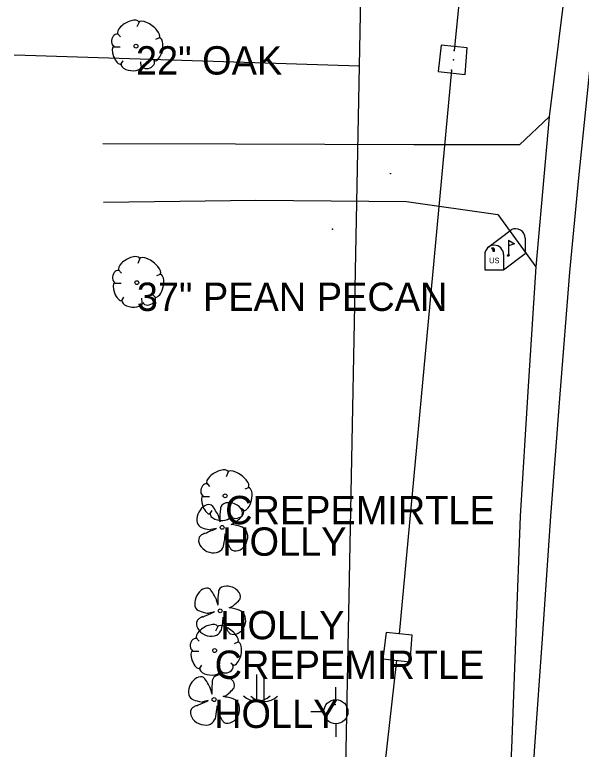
# Model space of a CAD drawing. Extents: x 1930288 to 1941089, y 588389 to 611475.
# Drawn here: x 1930774.6 to 1930874.5, y 598322 to 598451.6 of the extents above; entities that cross this region are included whole.
import ezdxf

# ---------------------------------------------------------------- set-up
doc = ezdxf.new("R2010")
doc.units = 0
for name, color, linetype in [('S_DRG_PT_SYM', 7, 'Continuous'), ('S_DRIVEWAY', 7, 'Continuous'), ('S_DROP_INLET', 7, 'Continuous'), ('S_EDGE_PAVEMENT', 7, 'Continuous'), ('S_GAS_UTILITIES', 7, 'Continuous'), ('S_MAILBOX', 7, 'Continuous'), ('S_MSC_PT_SYM', 7, 'Continuous'), ('S_SHOULDER', 7, 'Continuous'), ('S_STORM_SEWER', 7, 'Continuous'), ('S_TREE', 7, 'Continuous'), ('S_TREE_ANNOT', 7, 'Continuous'), ('S_UTILITY_POLE', 7, 'Continuous'), ('S_UTL_PT_SYM', 7, 'Continuous'), ('S_WATER_UTILITIES', 7, 'Continuous')]:
    doc.layers.add(name, color=color, linetype=linetype)

msp = doc.modelspace()

# ---------------------------------------------------------------- linework, layer by layer
at = {"layer": 'S_DRG_PT_SYM'}
msp.add_lwpolyline([(1930851.96, 598443.64), (1930851.96, 598443.69), (1930851.96, 598443.64), (1930851.91, 598443.64), (1930851.96, 598443.64), (1930851.96, 598443.59), (1930851.96, 598443.64), (1930852.01, 598443.64)], dxfattribs=at)
at = {"layer": 'S_DRIVEWAY'}
for points in [[(1930868.81, 598433.59), (1930863.6, 598428.65), (1930844.97, 598428.6), (1930829.25, 598428.67), (1930813.54, 598428.73), (1930790.14, 598428.8)], [(1930790.26, 598418.52), (1930803.67, 598418.69), (1930817.08, 598418.87), (1930830.39, 598418.75), (1930843.69, 598418.64), (1930859.8, 598416.35), (1930866.47, 598407.12)]]:
    msp.add_lwpolyline(points, dxfattribs=at)
at = {"layer": 'S_DROP_INLET'}
for points in [[(1930849.8, 598446.24), (1930849.25, 598441.56), (1930854.02, 598441.03), (1930854.39, 598445.77)], [(1930854.39, 598445.77), (1930849.8, 598446.24)], [(1930840.06, 598342.61), (1930839.52, 598337.93), (1930844.29, 598337.4), (1930844.66, 598342.14)], [(1930844.66, 598342.14), (1930840.06, 598342.61)]]:
    msp.add_lwpolyline(points, dxfattribs=at)
at = {"layer": 'S_EDGE_PAVEMENT'}
msp.add_lwpolyline([(1930877.33, 598456.1), (1930875.68, 598439.46), (1930874.03, 598422.82), (1930872.39, 598406.18), (1930870.73, 598384.64), (1930869.07, 598363.1), (1930867.63, 598342.37), (1930866.18, 598321.65), (1930865.17, 598301.92), (1930864.16, 598282.2), (1930863.63, 598267.31), (1930863.11, 598252.42), (1930862.8, 598239.89), (1930862.49, 598227.37)], dxfattribs=at)
at = {"layer": 'S_GAS_UTILITIES'}
msp.add_line((1930835.35, 598442.52), (1930774.62, 598444.47), dxfattribs=at)
at = {"layer": 'S_MAILBOX'}
for p, q in [((1930858.02, 598410.54), (1930862.15, 598413.65)), ((1930861.63, 598411.83), (1930861.63, 598409.11)), ((1930864.58, 598412.17), (1930864.58, 598409.46)), ((1930857.46, 598409.26), (1930857.46, 598406.55)), ((1930860.79, 598406.55), (1930864.58, 598409.46)), ((1930860.79, 598409.26), (1930860.79, 598406.55)), ((1930857.46, 598406.55), (1930860.79, 598406.55))]:
    msp.add_line(p, q, dxfattribs=at)
for points in [[(1930861.63, 598411.83), (1930862.74, 598411.16), (1930861.63, 598410.82)], [(1930858.65, 598410.38), (1930858.87, 598410.24), (1930858.87, 598409.85), (1930859.17, 598409.85), (1930859.17, 598410.21), (1930858.98, 598410.46), (1930858.65, 598410.41)]]:
    msp.add_lwpolyline(points, dxfattribs=at)
for centre, end in [((1930862.92, 598412.17), 117.5718), ((1930859.13, 598409.26), 180)]:
    msp.add_arc(centre, 1.66, 0, end, dxfattribs=at)
msp.add_ellipse((1930861.63, 598409.11), major_axis=(0.145, 0.132), ratio=0.564646, dxfattribs=at)
at = {"layer": 'S_MSC_PT_SYM'}
for points in [[(1930852.09, 598445.29), (1930852.09, 598445.34), (1930852.09, 598445.29), (1930852.04, 598445.29), (1930852.09, 598445.29), (1930852.09, 598445.24), (1930852.09, 598445.29), (1930852.14, 598445.29)], [(1930851.6, 598441.79), (1930851.6, 598441.84), (1930851.6, 598441.79), (1930851.55, 598441.79), (1930851.6, 598441.79), (1930851.6, 598441.74), (1930851.6, 598441.79), (1930851.65, 598441.79)], [(1930840.87, 598423.59), (1930840.87, 598423.64), (1930840.87, 598423.59), (1930840.82, 598423.59), (1930840.87, 598423.59), (1930840.87, 598423.54), (1930840.87, 598423.59), (1930840.92, 598423.59)], [(1930831.1, 598329.89), (1930831.1, 598329.94), (1930831.1, 598329.89), (1930831.05, 598329.89), (1930831.1, 598329.89), (1930831.1, 598329.84), (1930831.1, 598329.89), (1930831.15, 598329.89)]]:
    msp.add_lwpolyline(points, dxfattribs=at)
at = {"layer": 'S_SHOULDER'}
msp.add_lwpolyline([(1930871.29, 598453.49), (1930868.81, 598433.59), (1930867.64, 598420.35), (1930866.47, 598407.12), (1930865.09, 598385.12), (1930863.71, 598363.13), (1930862.94, 598342.62), (1930862.17, 598322.12), (1930861.08, 598302.35), (1930859.98, 598282.59), (1930857.48, 598272.25), (1930857.72, 598252.88), (1930859.2, 598240.14), (1930860.69, 598227.4)], dxfattribs=at)
at = {"layer": 'S_STORM_SEWER'}
for p, q in [((1930861.75, 598545.64), (1930852.09, 598445.29)), ((1930851.6, 598441.79), (1930842.36, 598342.37)), ((1930841.9, 598337.67), (1930828.48, 598218.96))]:
    msp.add_line(p, q, dxfattribs=at)
at = {"layer": 'S_TREE'}
for p, q in [((1930796.51, 598450.28), (1930796.13, 598449.42)), ((1930792.72, 598448.26), (1930793.22, 598447.68)), ((1930800.08, 598447.49), (1930799.42, 598447.21)), ((1930792.06, 598445.94), (1930793.18, 598445.94)), ((1930799.3, 598443.38), (1930798.84, 598443.8)), ((1930793.22, 598442.76), (1930793.68, 598443.46)), ((1930796.9, 598442.49), (1930796.82, 598443.26)), ((1930796.67, 598408.56), (1930796.28, 598407.71)), ((1930792.87, 598406.55), (1930793.38, 598405.97)), ((1930800.24, 598405.77), (1930799.58, 598405.5)), ((1930792.22, 598404.22), (1930793.34, 598404.22)), ((1930793.38, 598401.04), (1930793.84, 598401.74)), ((1930797.06, 598400.77), (1930796.98, 598401.55)), ((1930799.46, 598401.66), (1930799, 598402.09)), ((1930812.24, 598370.93), (1930811.85, 598370.08)), ((1930808.44, 598368.92), (1930808.95, 598368.33)), ((1930815.81, 598368.14), (1930815.15, 598367.87)), ((1930807.79, 598366.59), (1930808.91, 598366.59)), ((1930808.95, 598363.41), (1930809.41, 598364.11)), ((1930812.63, 598363.14), (1930812.55, 598363.92)), ((1930815.03, 598364.03), (1930814.57, 598364.46)), ((1930810.8, 598362.11), (1930810.55, 598363)), ((1930810.15, 598360.95), (1930809.17, 598360.73)), ((1930812.74, 598361.65), (1930813.12, 598361.81)), ((1930811.68, 598360.01), (1930811.76, 598359.58)), ((1930810.43, 598347.38), (1930810.19, 598348.28)), ((1930812.38, 598346.92), (1930812.76, 598347.09)), ((1930809.79, 598346.22), (1930808.81, 598346)), ((1930811.32, 598345.29), (1930811.4, 598344.85)), ((1930810.39, 598343.65), (1930810, 598342.8)), ((1930806.59, 598341.63), (1930807.09, 598341.05)), ((1930813.95, 598340.86), (1930813.29, 598340.59)), ((1930805.93, 598339.31), (1930807.06, 598339.31)), ((1930807.09, 598336.13), (1930807.56, 598336.83)), ((1930810.78, 598335.86), (1930810.7, 598336.64)), ((1930813.18, 598336.75), (1930812.71, 598337.18)), ((1930809.37, 598331.73), (1930809.13, 598332.62)), ((1930811.32, 598331.27), (1930811.7, 598331.43)), ((1930808.72, 598330.56), (1930807.75, 598330.35)), ((1930810.26, 598329.63), (1930810.34, 598329.19))]:
    msp.add_line(p, q, dxfattribs=at)
for centre in [(1930795.96, 598446.03), (1930796.11, 598404.32), (1930811.68, 598366.69), (1930811.16, 598361.13), (1930810.8, 598346.4), (1930809.83, 598339.4), (1930809.74, 598330.75)]:
    msp.add_circle(centre, 0.341, dxfattribs=at)
for centre, major_axis, ratio, start_param, end_param in [((1930794.62, 598449.23), (1.86, 1.08), 0.471018, 0, 3.141593), ((1930798.27, 598448.91), (-1.81, 1.36), 0.405113, 3.141593, 6.283186), ((1930792.38, 598447.12), (0.31, 1.03), 0.646762, 0, 3.141593), ((1930799.63, 598445.5), (0.46, 2.04), 0.482994, 3.141593, 6.283185), ((1930792.69, 598444.47), (-0.61, 1.6), 0.420543, 6.283185, 9.424777), ((1930795.15, 598442.69), (-1.83, 0.19), 0.529943, 0, 3.141593), ((1930798.11, 598442.98), (1.09, 0.46), 0.711534, 3.141592, 6.283185), ((1930794.78, 598407.52), (1.86, 1.08), 0.471018, 0, 3.141593), ((1930798.43, 598407.2), (-1.81, 1.36), 0.405113, 3.141593, 6.283186), ((1930792.54, 598405.4), (0.31, 1.03), 0.646762, 0, 3.141593), ((1930799.79, 598403.79), (0.46, 2.04), 0.482994, 3.141593, 6.283185), ((1930792.85, 598402.75), (-0.61, 1.6), 0.420543, 6.283185, 9.424777), ((1930795.31, 598400.97), (-1.83, 0.19), 0.529943, 0, 3.141593), ((1930798.27, 598401.27), (1.09, 0.46), 0.711534, 3.141592, 6.283185), ((1930810.35, 598369.89), (1.86, 1.08), 0.471018, 0, 3.141593), ((1930814, 598369.56), (-1.81, 1.36), 0.405113, 3.141593, 6.283186), ((1930808.11, 598367.77), (0.31, 1.03), 0.646762, 0, 3.141593), ((1930815.36, 598366.16), (0.46, 2.04), 0.482994, 3.141593, 6.283185), ((1930808.42, 598365.12), (-0.61, 1.6), 0.420543, 6.283185, 9.424777), ((1930808.28, 598363.15), (-1.03, -1.88), 0.662338, 3.141593, 6.283185), ((1930809.93, 598364.02), (0.62, -1.01), 0.083512, 0, 3.141593), ((1930810.86, 598363.43), (-0.07, -1.33), 0.068203, 3.141593, 6.283185), ((1930812.82, 598364.02), (1.89, -0.74), 0.673998, 0, 3.141593), ((1930810.88, 598363.34), (-1.83, 0.19), 0.529943, 0, 3.141593), ((1930813.84, 598363.63), (1.09, 0.46), 0.711534, 3.141592, 6.283185), ((1930813.92, 598362.54), (-0.798, -0.73), 0.092159, 0, 3.141593), ((1930808.21, 598361), (0.964, -0.267), 0.113563, 3.141593, 6.283185), ((1930809.11, 598360.5), (1.04, 0.44), 0.002756, 3.141593, 6.283185), ((1930813.7, 598361.42), (0.96, -0.23), 0.056001, 0, 3.141593), ((1930813.78, 598359.14), (0.88, 2.05), 0.81717, 3.141593, 6.283185), ((1930809.19, 598358.47), (2.07, -0.93), 0.760068, 3.141593, 6.283185), ((1930807.59, 598359.73), (0.477, 0.328), 0.136309, 0, 3.141593), ((1930811.44, 598358.85), (0.19, 1.31), 0.114148, 3.141593, 5.822668), ((1930812.01, 598358.8), (0.254, -0.771), 0.051603, 3.141593, 6.283185), ((1930812.59, 598357.57), (-0.321, 0.467), 0.094289, 0, 3.141593), ((1930807.92, 598348.42), (-1.03, -1.88), 0.662338, 3.141593, 6.283185), ((1930809.57, 598349.29), (0.62, -1.01), 0.083512, 0, 3.141593), ((1930812.46, 598349.29), (1.89, -0.74), 0.673998, 0, 3.141593), ((1930810.5, 598348.71), (-0.07, -1.33), 0.068203, 3.141593, 6.283185), ((1930813.56, 598347.82), (-0.798, -0.73), 0.092159, 0, 3.141593), ((1930807.85, 598346.27), (0.964, -0.267), 0.113563, 3.141593, 6.283185), ((1930813.34, 598346.69), (0.96, -0.23), 0.056001, 0, 3.141593), ((1930813.42, 598344.42), (0.88, 2.05), 0.81717, 3.141593, 6.283185), ((1930807.23, 598345.01), (0.477, 0.328), 0.136309, 0, 3.141593), ((1930808.75, 598345.78), (1.04, 0.44), 0.002756, 3.141593, 6.283185), ((1930811.08, 598344.12), (0.19, 1.31), 0.114148, 3.141593, 5.822668), ((1930808.49, 598342.61), (1.86, 1.08), 0.471018, 0, 3.141593), ((1930808.82, 598343.74), (2.07, -0.93), 0.760068, 3.141593, 6.283185), ((1930812.15, 598342.28), (-1.81, 1.36), 0.405113, 3.141593, 6.283186), ((1930811.65, 598344.08), (0.254, -0.771), 0.051603, 3.141593, 6.283185), ((1930812.23, 598342.84), (-0.321, 0.467), 0.094289, 0, 3.141593), ((1930806.26, 598340.49), (0.31, 1.03), 0.646762, 0, 3.141593), ((1930813.5, 598338.87), (0.46, 2.04), 0.482994, 3.141593, 6.283185), ((1930806.56, 598337.84), (-0.61, 1.6), 0.420543, 6.283185, 9.424777), ((1930809.03, 598336.06), (-1.83, 0.19), 0.529943, 0, 3.141593), ((1930811.98, 598336.35), (1.09, 0.46), 0.711534, 3.141592, 6.283185), ((1930806.85, 598332.77), (-1.03, -1.88), 0.662338, 3.141593, 6.283185), ((1930811.4, 598333.63), (1.89, -0.74), 0.673998, 0, 3.141593), ((1930808.51, 598333.63), (0.62, -1.01), 0.083512, 0, 3.141593), ((1930809.44, 598333.05), (-0.07, -1.33), 0.068203, 3.141593, 6.283185), ((1930812.5, 598332.16), (-0.798, -0.73), 0.092159, 0, 3.141593), ((1930806.79, 598330.61), (0.964, -0.267), 0.113563, 3.141593, 6.283185), ((1930812.28, 598331.04), (0.96, -0.23), 0.056001, 0, 3.141593), ((1930812.36, 598328.76), (0.88, 2.05), 0.81717, 3.141593, 6.283185), ((1930806.17, 598329.35), (0.477, 0.328), 0.136309, 0, 3.141593), ((1930807.69, 598330.12), (1.04, 0.44), 0.002756, 3.141593, 6.283185), ((1930810.02, 598328.47), (0.19, 1.31), 0.114148, 3.141593, 5.822668), ((1930807.76, 598328.09), (2.07, -0.93), 0.760068, 3.141593, 6.283185), ((1930810.59, 598328.42), (0.254, -0.771), 0.051603, 3.141593, 6.283185), ((1930811.17, 598327.19), (-0.321, 0.467), 0.094289, 0, 3.141593)]:
    msp.add_ellipse(centre, major_axis=major_axis, ratio=ratio, start_param=start_param, end_param=end_param, dxfattribs=at)
at = {"layer": 'S_UTILITY_POLE'}
for p, q in [((1930817.21, 598335.19), (1930817.21, 598330.46)), ((1930818.51, 598335.16), (1930818.51, 598330.43)), ((1930831.2, 598330.72), (1930831.2, 598332.97)), ((1930829.11, 598328.59), (1930826.79, 598328.59)), ((1930831.28, 598324.17), (1930831.28, 598326.5))]:
    msp.add_line(p, q, dxfattribs=at)
msp.add_circle((1930831.21, 598328.61), 2.13, dxfattribs=at)
for centre in [(1930817.28, 598333.88), (1930818.57, 598333.85)]:
    msp.add_arc(centre, 3.41, 226.3972, 313.6028, dxfattribs=at)
at = {"layer": 'S_UTL_PT_SYM'}
for points in [[(1930852.09, 598445.29), (1930852.09, 598445.34), (1930852.09, 598445.29), (1930852.04, 598445.29), (1930852.09, 598445.29), (1930852.09, 598445.24), (1930852.09, 598445.29), (1930852.14, 598445.29)], [(1930774.62, 598444.47), (1930774.62, 598444.52), (1930774.62, 598444.47), (1930774.57, 598444.47), (1930774.62, 598444.47), (1930774.62, 598444.42), (1930774.62, 598444.47), (1930774.67, 598444.47)], [(1930851.96, 598443.64), (1930851.96, 598443.69), (1930851.96, 598443.64), (1930851.91, 598443.64), (1930851.96, 598443.64), (1930851.96, 598443.59), (1930851.96, 598443.64), (1930852.01, 598443.64)], [(1930835.35, 598442.52), (1930835.35, 598442.57), (1930835.35, 598442.52), (1930835.3, 598442.52), (1930835.35, 598442.52), (1930835.35, 598442.47), (1930835.35, 598442.52), (1930835.4, 598442.52)], [(1930851.6, 598441.79), (1930851.6, 598441.84), (1930851.6, 598441.79), (1930851.55, 598441.79), (1930851.6, 598441.79), (1930851.6, 598441.74), (1930851.6, 598441.79), (1930851.65, 598441.79)], [(1930830.61, 598413.74), (1930830.61, 598413.79), (1930830.61, 598413.74), (1930830.56, 598413.74), (1930830.61, 598413.74), (1930830.61, 598413.69), (1930830.61, 598413.74), (1930830.66, 598413.74)]]:
    msp.add_lwpolyline(points, dxfattribs=at)
at = {"layer": 'S_WATER_UTILITIES'}
msp.add_line((1930835.68, 598459.98), (1930831.37, 598238.21), dxfattribs=at)

# ---------------------------------------------------------------- texts
at = {"layer": 'S_MAILBOX'}
msp.add_text('US', height=0.96, rotation=360, dxfattribs=at).set_placement((1930858.23, 598407.74))
at = {"layer": 'S_TREE_ANNOT'}
for s, p in [('22" OAK', (1930795.96, 598441.03)), ('37" PEAN PECAN', (1930796.11, 598399.32)), ('CREPEMIRTLE', (1930811.68, 598361.69)), ('HOLLY', (1930811.16, 598356.13)), ('HOLLY', (1930810.8, 598341.4)), ('CREPEMIRTLE', (1930809.83, 598334.4)), ('HOLLY', (1930809.74, 598325.75))]:
    msp.add_text(s, height=5, dxfattribs=at).set_placement(p)

doc.saveas('drawing.dxf')
